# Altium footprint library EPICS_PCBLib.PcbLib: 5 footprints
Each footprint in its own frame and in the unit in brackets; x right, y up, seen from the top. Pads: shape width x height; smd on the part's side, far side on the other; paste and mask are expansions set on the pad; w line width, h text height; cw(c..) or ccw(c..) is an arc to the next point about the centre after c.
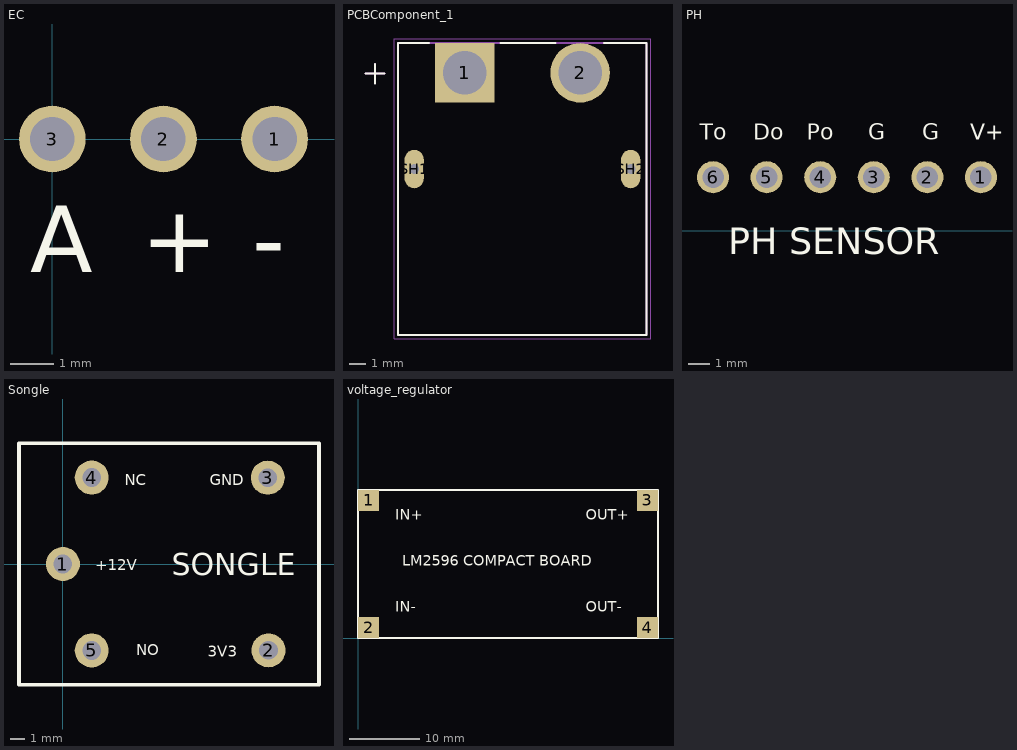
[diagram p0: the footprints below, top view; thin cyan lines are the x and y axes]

## EC [mil]
pads (3):
  round 60 hole 40: 1(200,0) 2(100,0) 3(0,0)
Top Overlay:
  text "A" at -20,-120 h60
  text "+" at 80,-120 h60
  text "-" at 180,-119.99 h60

## PCBComponent_1 [mm]
pads (4):
  rect 3.716x3.716 / inner round 3.716 / far side rect 3.716x3.716 hole 2.7 mask+0.102: 1(34.904,-40.704)
  round 3.716 hole 2.7 mask+0.102: 2(42.104,-40.704)
  oval 1.2x2.4 hole 0.6 square mask+0.102: SH1(31.754,-46.704) SH2(45.254,-46.704)
Top Overlay:
  lines w0.127: 28.704,-40.754 29.904,-40.754 ; 29.304,-41.354 29.304,-40.154 ; 32.676,-38.854 30.754,-38.854 30.754,-57.054 46.254,-57.054 46.254,-38.854 43.582,-38.854 ; 37.132,-38.854 40.576,-38.854
Mechanical 13:
  lines w0.127: 28.704,-40.754 29.904,-40.754 ; 29.304,-41.354 29.304,-40.154 ; 30.754,-57.054 30.754,-38.854 46.254,-38.854 46.254,-57.054 30.754,-57.054
Mechanical 15:
  lines w0.05: 30.504,-57.304 30.504,-38.594 46.504,-38.594 46.504,-57.304 30.504,-57.304
3D body "step_temp.STEP": height 8.4, standoff -2.55, extent 30.754,-57.054 46.254,-38.854

## PH [mil]
pads (6):
  round 60 hole 40: 1(880,100) 2(780,100) 3(680,100) 4(580,100) 5(480,100) 6(380,100)
Top Overlay:
  text "PH SENSOR" at 408.7,-44.06 h50
  text "G" at 670,170 h30
  text "V+" at 860,170 h30
  text "G" at 770,170 h30
  text "Do" at 455,170 h30
  text "Po" at 555,170 h30
  text "To" at 355,170 h30

## Songle [mil]
pads (5):
  round 93 hole 51: 1(0,0) 2(562,-236) 3(560,236) 4(78.74,236.22) 5(78.74,-236.22)
Top Overlay:
  lines w10: -120,-330 700,-330 700,330 -120,330 -120,-330
  text "3V3" at 396,-254 h30
  text "SONGLE" at 298,-31 h60
  text "NO" at 201,-250 h30
  text "+12V" at 88,-17 h30
  text "NC" at 169,215 h30
  text "GND" at 402,215 h30

## voltage_regulator [mil]
pads (4):
  rect 118x118 smd: 1(59.06,767.72) 2(59.06,59.06) 3(1614.17,767.72) 4(1614.17,59.06)
Top Overlay:
  lines w10: 0,0 1673.23,0 1673.23,826.77 0,826.77 0,0
  text "IN+" at 206.85,659.61 h60
  text "IN-" at 206.85,147.8 h60
  text "OUT+" at 1269.84,659.61 h60
  text "OUT-" at 1269.84,147.8 h60
  text "LM2596 COMPACT BOARD" at 246.22,403.7 h60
